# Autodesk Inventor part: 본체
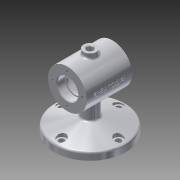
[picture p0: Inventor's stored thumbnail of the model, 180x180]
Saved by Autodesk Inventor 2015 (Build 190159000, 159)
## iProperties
Created: 2018-12
Part Number: 본체
Material: 알루미늄 6061
Document SubType Name: Modeling
Designer: now
Density: 2.7 g/cm^3
Appearance: 알루미늄 - 평지
Mass: 685.089 g
Surface Area: 555.482 cm^2
Volume: 253.737 cm^3
Author: now
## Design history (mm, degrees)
sketch "스케치1"
  geometry: L1 (0, 0)-(0, -25.737); L2 (0, 0)-(-55, -14.737); L3 (0, -25.737)-(-55, -25.737); L4 (-55, -14.737)-(-55, -25.737)
  constraints: 8 end point, 2 vertical, 1 horizontal
  dimensions: "d0" = 11 distance of L2.end L3.end; "d1" = 55 distance of L1.end L3.end; "d3" = 75 deg angle of L4 L2
revolve "회전1" sketch "스케치1" stored, may be unused: angle "d4" = 90 deg
sketch "스케치2"
  geometry: C1 r 55 at (0, 0) reference; C2 r 12 at (0, 0)
  constraints: 1 centre point, 1 coincident
  dimensions: "d5" = 24 diameter of C2
extrude "돌출1" join sketch "스케치2" distance "d6" = 75; taper "d7" = 0 deg
sketch "스케치3"
  geometry: L1 (-35, 79.263)-(35, 79.263); L2 (35, 79.263)-(35, 49.263); L3 (35, 49.263)-(-35, 49.263); L4 (-35, 49.263)-(-35, 79.263); L5 (12, 49.263)-(-12, 49.263) reference; 2 further points
  constraints: 8 end point, 2 midpoint, 2 parallel, 1 horizontal, 1 perpendicular
  dimensions: "d9" = 60 diameter of L1 L3; "d10" = 35 distance of L3.end point (0, 49.263); "d11" = 70 distance of L1.start L1.end
revolve "회전2" sketch "스케치3" stored, may be unused: angle "d12" = 90 deg
node "작업 평면1"
sketch "스케치4"
  geometry: C1 r 10 at (0, 0); 1 further point
  constraints: 1 centre point, 1 coincident
  dimensions: "d14" = 20 diameter of C1
extrude "돌출2" join sketch "스케치4" stored distance "d15" = 75; taper "d16" = 0 deg
sketch "스케치5"
  geometry: L1 (-35, 19.263)-(-35, 79.263) reference; L2 (-35, 49.263)-(35, 49.263); L3 (35, 19.263)-(35, 79.263) reference; L4 (-35, 65.263)-(-23.3, 65.263); L5 (-23, 64.963)-(-23, 63.263); L6 (-23, 63.263)-(-20, 63.263); L7 (-20, 63.263)-(-20, 71.263); L8 (-17, 74.263)-(17, 74.263); L9 (20, 71.263)-(20, 63.263); L10 (20, 63.263)-(23, 63.263); L11 (23, 63.263)-(23, 64.963); L12 (23.3, 65.263)-(35, 65.263); A1 r 3 centre (-17, 71.263) between (-17, 74.263) and (-20, 71.263); A2 r 3 centre (17, 71.263) between (20, 71.263) and (17, 74.263); A3 r 0.3 centre (-23.3, 64.963) between (-23, 64.963) and (-23.3, 65.263); A4 r 0.3 centre (23.3, 64.963) between (23.3, 65.263) and (23, 64.963); 5 further points
  constraints: 20 end point, 14 point on line, 8 point on circle, 8 tangent, 4 centre point, 4 vertical, 3 horizontal, 2 equal radius, 2 midpoint
  dimensions: "d17" = 32 diameter of L4 L2; "d18" = 28 diameter of L6 L2; "d19" = 50 diameter of L8 L2; "d20" = 12 distance of L4.start point (-23, 65.263); "d21" = 3 distance of L5.end L6.end; "d22" = 40 distance of point (-20, 74.263) point (20, 74.263); "d23" = 3 distance of L9.end L10.end; "d24" = 3 radius of A1; "d25" = 0.3 radius of A3
revolve "회전3" sketch "스케치5" stored, may be unused: angle "d26" = 90 deg
sketch "스케치6"
  geometry: C1 r 10 at (0, 0) reference; C2 r 5 at (0, 0)
  constraints: 1 centre point, 1 coincident
  dimensions: "d27" = 10 diameter of C2
extrude "돌출3" cut sketch "스케치6" stored distance "d28" = 75; taper "d29" = 0 deg
sketch "스케치7" dims "d30" = 88
  geometry: C1 r 55 at (0, 0) reference; C2 r 4.5 at (-44, 0); 1 further point
  constraints: 2 horizontal alignment, 1 centre point, 1 coincident, 2 other
  dimensions: "d31" = 9 diameter of C2
extrude "돌출4" cut sketch "스케치7" distance "d32" = 10; taper "d33" = 0 deg
sketch "스케치8"
  geometry: C1 r 4.5 at (0, 0) reference; C2 r 7 at (0, 0); 1 further point
  constraints: 1 centre point, 1 coincident
  dimensions: "d34" = 14 diameter of C2
extrude "돌출5" cut sketch "스케치8" distance "d35" = 10; taper "d36" = 0 deg
fillet "모깎기1" dims "d40" = 3
chamfer "모따기1" distance "d41" = 1; stored, may be unused: second distance "d42" = 2, angle "d43" = 45 deg
chamfer "모따기2" distance "d44" = 1; stored, may be unused: second distance "d45" = 2, angle "d46" = 45 deg
sketch "스케치9"
  geometry: C1 r 30 at (0, 0) reference; 2 further points
  constraints: 1 vertical alignment
  dimensions: "d47" = 23 distance of C1.centre point (0, 23)
hole "구멍1" sketch "스케치9" at (0, 23) diameter "d48" = 3.242; stored, may be unused: countersink angle "d52" = 90 deg, drill point angle "d54" = 118 deg; dims "d49" = 8, "d50" = 4, "d51" = 2, "d53" = 10
sketch "스케치10"
  geometry: C1 r 30 at (0, 0) reference; 2 further points
  constraints: 1 vertical alignment
  dimensions: "d58" = 23 distance of C1.centre point (0, -23)
hole "구멍2" sketch "스케치10" at (0, -23) diameter "d59" = 3.242; stored, may be unused: countersink angle "d63" = 90 deg, drill point angle "d65" = 118 deg; dims "d60" = 8, "d61" = 4, "d62" = 2, "d64" = 10
fillet "모깎기2" dims "d69" = 3
node "작업 평면2"
sketch "스케치11"
  geometry: L1 (-35, 19.263)-(-35, 79.263) reference; 2 further points
  constraints: 1 other
  dimensions: "d71" = 35 distance from line of L1 point (0, 49.263); "d72" = 30 vertical distance of L1.end point (0, 49.263)
feature "엠보싱1" sketch "스케치11" dims "d0" = 11, "d1" = 55, "d3" = 75 deg, "d73" = 0.5, "d74" = 0
fillet "모깎기3" dims "d75" = 3
node "솔리드1"
pattern_circular "원형 패턴1" dims angle "d38" = 360 deg
pattern_circular "원형 패턴2" dims angle "d56" = 360 deg
pattern_circular "원형 패턴3" dims angle "d67" = 360 deg
other parameters: "d13" = -112, "d70" = 45.75
